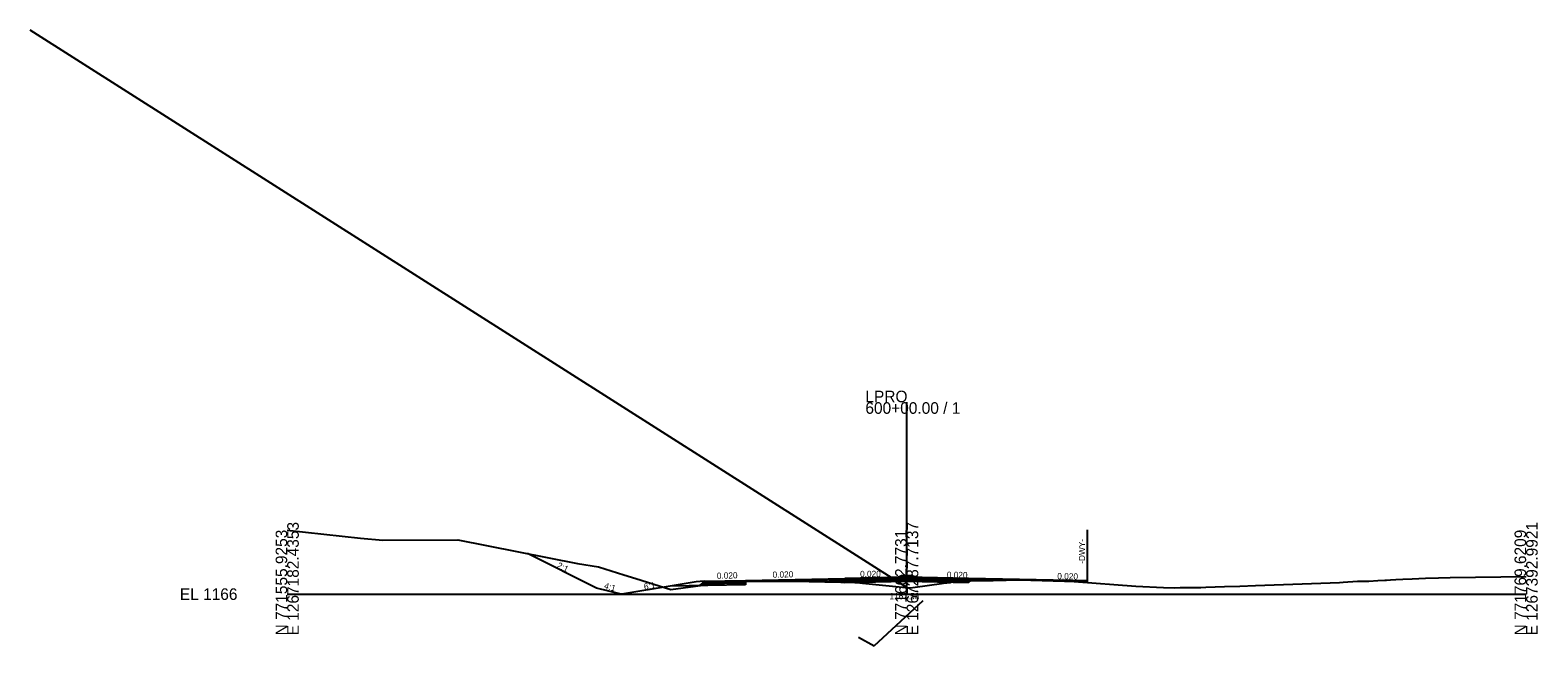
# Model space of a CAD drawing. Extents: x -3833 to 1267678, y -522 to 773248.
# Drawn here: x 937.8 to 1302.8, y 987.5 to 1136.6 of the extents above; entities that cross this region are included whole.
import ezdxf

# ---------------------------------------------------------------- set-up
doc = ezdxf.new("R2010")
doc.units = 0
for name, color, linetype in [('Exist Cross Section Cell', 7, 'Continuous'), ('Exist XS Center Line Elevation Label', 7, 'Continuous'), ('Exist XS Ground Line', 7, 'Continuous'), ('Prop CMT DNC', 7, 'Continuous'), ('Prop CMT Pvmt Course 1', 7, 'Continuous'), ('Prop CMT Pvmt Course 2', 7, 'Continuous'), ('Prop CMT Pvmt Course 4', 7, 'Continuous'), ('Prop CMT Shld Paved Course 1', 7, 'Continuous'), ('Prop CMT Shld Paved Course 2', 7, 'Continuous'), ('Prop CMT Shld Paved Course 4', 7, 'Continuous'), ('Prop CMT Slope Grass', 7, 'Continuous'), ('Prop CMT Subgrade Earthwork', 7, 'Continuous'), ('Prop Conc Curb and Gutter', 7, 'Continuous'), ('Prop Corridor Mesh Bottom', 7, 'Continuous'), ('Prop XS Ditch Slope Text', 7, 'Continuous'), ('Prop XS Finish Grade', 7, 'Continuous'), ('Prop XS SE Text', 7, 'Continuous'), ('Prop XS Shear Point Element', 7, 'Continuous'), ('Prop XS Shear Point Label', 7, 'Continuous'), ('Scratch_Level_1', 7, 'Continuous'), ('Scratch_Level_5', 7, 'Continuous')]:
    doc.layers.add(name, color=color, linetype=linetype)

msp = doc.modelspace()

# ---------------------------------------------------------------- linework, layer by layer
at = {"layer": 'Exist Cross Section Cell'}
for p, q in [((1150, 1000), (1150, 1046.49)), ((1000, 1000), (1150, 1000)), ((1150, 1000), (1300, 1000))]:
    msp.add_line(p, q, dxfattribs=at)
at = {"layer": 'Exist XS Ground Line'}
for p, q in [((1000, 1015.5), (1017.77, 1013.59)), ((1017.77, 1013.59), (1023.18, 1013.11)), ((1023.18, 1013.11), (1041.35, 1013.17)), ((1041.35, 1013.17), (1070.26, 1007.43)), ((1070.26, 1007.43), (1075.35, 1006.63)), ((1075.35, 1006.63), (1081.51, 1004.66)), ((1081.51, 1004.66), (1084.42, 1003.76)), ((1278.81, 1003.94), (1281.57, 1004.02)), ((1281.57, 1004.02), (1300, 1004.27)), ((1084.42, 1003.76), (1092.93, 1001.15)), ((1092.93, 1001.15), (1104.86, 1002.77)), ((1104.86, 1002.77), (1106.77, 1002.98)), ((1106.77, 1002.98), (1109.97, 1003.12)), ((1109.97, 1003.12), (1110.46, 1003.12)), ((1110.46, 1003.12), (1111.83, 1003.13)), ((1111.83, 1003.13), (1122.5, 1003.16)), ((1122.5, 1003.16), (1134.09, 1002.93)), ((1134.09, 1002.93), (1135.87, 1002.89)), ((1135.87, 1002.89), (1136.2, 1002.87)), ((1136.2, 1002.87), (1138.68, 1002.74)), ((1138.68, 1002.74), (1139.33, 1002.67)), ((1139.33, 1002.67), (1149.03, 1001.67)), ((1149.03, 1001.67), (1150, 1001.58)), ((1150, 1001.58), (1150.87, 1001.49)), ((1150.87, 1001.49), (1152.03, 1001.66)), ((1152.03, 1001.66), (1158.46, 1002.61)), ((1158.46, 1002.61), (1158.92, 1002.66)), ((1158.92, 1002.66), (1160.5, 1002.85)), ((1160.5, 1002.85), (1160.9, 1003.08)), ((1160.9, 1003.08), (1163.34, 1003.19)), ((1163.34, 1003.19), (1164.61, 1003.25)), ((1164.61, 1003.25), (1164.95, 1003.24)), ((1164.95, 1003.24), (1165.49, 1003.25)), ((1165.49, 1003.25), (1170.95, 1003.33)), ((1170.95, 1003.33), (1177.29, 1003.43)), ((1177.29, 1003.43), (1188.21, 1003.17)), ((1188.21, 1003.17), (1189.39, 1003.14)), ((1189.39, 1003.14), (1190.57, 1003.07)), ((1190.57, 1003.07), (1205.46, 1001.91)), ((1205.46, 1001.91), (1212.19, 1001.57)), ((1212.19, 1001.57), (1214.82, 1001.56)), ((1214.82, 1001.56), (1216.21, 1001.57)), ((1216.21, 1001.57), (1218.06, 1001.58)), ((1218.06, 1001.58), (1219.86, 1001.6)), ((1219.86, 1001.6), (1221.24, 1001.62)), ((1221.24, 1001.62), (1222.43, 1001.69)), ((1222.43, 1001.69), (1226.96, 1001.85)), ((1226.96, 1001.85), (1230.69, 1001.94)), ((1230.69, 1001.94), (1234.49, 1002.07)), ((1234.49, 1002.07), (1254.8, 1002.84)), ((1254.8, 1002.84), (1255.7, 1002.93)), ((1255.7, 1002.93), (1259.14, 1003.1)), ((1259.14, 1003.1), (1261.92, 1003.16)), ((1261.92, 1003.16), (1264.13, 1003.29)), ((1264.13, 1003.29), (1265.75, 1003.36)), ((1265.75, 1003.36), (1266.22, 1003.39)), ((1266.22, 1003.39), (1267.15, 1003.45)), ((1267.15, 1003.45), (1268.43, 1003.51)), ((1268.43, 1003.51), (1270.14, 1003.61)), ((1270.14, 1003.61), (1272.44, 1003.73)), ((1272.44, 1003.73), (1275.61, 1003.84)), ((1275.61, 1003.84), (1278.81, 1003.94))]:
    msp.add_line(p, q, dxfattribs=at)
at = {"layer": 'Prop CMT Pvmt Course 1'}
for p, q in [((1147.75, 1004.06), (1147, 1004.05)), ((1152.82, 1004.05), (1153, 1004.05)), ((1111, 1003.33), (1135, 1003.81)), ((1111, 1003.12), (1111, 1003.33)), ((1111, 1003.33), (1111, 1003.33)), ((1135, 1003.81), (1135, 1003.81)), ((1135, 1003.81), (1135, 1003.81)), ((1135, 1003.81), (1135, 1003.56)), ((1135, 1003.56), (1135, 1003.56)), ((1147, 1003.8), (1147.75, 1003.81)), ((1153, 1003.8), (1152.82, 1003.8)), ((1193.7, 1003.23), (1165, 1003.81)), ((1165, 1003.81), (1165, 1003.81)), ((1165, 1003.81), (1165, 1003.24)), ((1165, 1003.56), (1177.29, 1003.43)), ((1189.78, 1003.12), (1193.7, 1002.98)), ((1193.7, 1002.98), (1193.7, 1003.23)), ((1193.7, 1003.23), (1193.7, 1003.23)), ((1193.7, 1003.23), (1193.7, 1003.23)), ((1193.7, 1002.98), (1193.7, 1002.98))]:
    msp.add_line(p, q, dxfattribs=at)
at = {"layer": 'Prop CMT Pvmt Course 2'}
for p, q in [((1150, 1003.86), (1135, 1003.56)), ((1135, 1003.56), (1135, 1003.56)), ((1135, 1003.56), (1135, 1003.23)), ((1135, 1003.22), (1150, 1003.53)), ((1135, 1003.23), (1135, 1003.22)), ((1147.75, 1003.81), (1147, 1003.8)), ((1165, 1003.56), (1150, 1003.86)), ((1150, 1003.86), (1150, 1003.86)), ((1150, 1003.86), (1150, 1003.86)), ((1150, 1003.53), (1150, 1003.53)), ((1150, 1003.53), (1150, 1003.53)), ((1150, 1003.53), (1165, 1003.22)), ((1152.25, 1003.81), (1152.82, 1003.8)), ((1152.82, 1003.8), (1153, 1003.8)), ((1165, 1003.56), (1165, 1003.56)), ((1165, 1003.22), (1165, 1003.22))]:
    msp.add_line(p, q, dxfattribs=at)
at = {"layer": 'Prop CMT Pvmt Course 4'}
for p, q in [((1147, 1004.05), (1147, 1003.01)), ((1148, 1004.07), (1148, 1003.03)), ((1152, 1004.07), (1152, 1003.03)), ((1153, 1004.05), (1153, 1003.01)), ((1135, 1002.76), (1135, 1003.23)), ((1135, 1003.23), (1135, 1003.23)), ((1135, 1003.23), (1135, 1003.22)), ((1150, 1003.53), (1150, 1003.53)), ((1150, 1003.53), (1150, 1003.53)), ((1165, 1003.22), (1165, 1003.22)), ((1165, 1003.22), (1165, 1003.22))]:
    msp.add_line(p, q, dxfattribs=at)
at = {"layer": 'Prop CMT Shld Paved Course 1'}
for p, q in [((1150, 1004.11), (1135, 1003.81)), ((1165, 1003.81), (1150, 1004.11)), ((1150, 1004.11), (1150, 1004.11)), ((1150, 1004.11), (1150, 1004.11)), ((1150, 1004.11), (1150, 1004.11)), ((1150, 1004.11), (1150, 1004.11)), ((1100.74, 1002.87), (1101, 1003.13)), ((1111, 1003.08), (1100.74, 1002.87)), ((1101, 1003.13), (1111, 1003.33)), ((1101, 1003.13), (1101, 1003.13)), ((1111, 1003.33), (1111, 1003.33)), ((1111, 1003.33), (1111, 1003.33)), ((1111, 1003.33), (1111, 1003.08)), ((1111, 1003.08), (1111, 1003.08)), ((1135, 1003.81), (1135, 1003.81)), ((1135, 1003.81), (1135, 1003.56)), ((1150, 1003.86), (1150, 1003.86)), ((1150, 1003.86), (1150, 1003.86)), ((1150, 1003.86), (1150, 1003.86)), ((1165, 1003.56), (1165, 1003.81)), ((1165, 1003.81), (1165, 1003.81))]:
    msp.add_line(p, q, dxfattribs=at)
at = {"layer": 'Prop CMT Shld Paved Course 2'}
for p, q in [((1100.4, 1002.53), (1100.74, 1002.87)), ((1100.74, 1002.87), (1100.74, 1002.87)), ((1111, 1003.08), (1111, 1003.08)), ((1111, 1003.08), (1111, 1003.08)), ((1111, 1002.74), (1111, 1002.74)), ((1113.8, 1003.13), (1122.5, 1003.16)), ((1113.8, 1003.13), (1113.8, 1003.13)), ((1122.5, 1003.31), (1113.81, 1003.13)), ((1135, 1003.56), (1122.5, 1003.31)), ((1122.5, 1003.31), (1122.5, 1003.31)), ((1122.5, 1003.16), (1122.5, 1003.16)), ((1122.5, 1003.16), (1122.5, 1003.16)), ((1122.5, 1003.16), (1127.2, 1003.07)), ((1127.2, 1003.07), (1135, 1003.22)), ((1127.2, 1003.07), (1127.2, 1003.07)), ((1134.09, 1003.54), (1134.09, 1003.54)), ((1134.09, 1003.2), (1134.09, 1003.2)), ((1135, 1003.22), (1135, 1003.56)), ((1135, 1003.56), (1135, 1003.56)), ((1165, 1003.56), (1165, 1003.56)), ((1165, 1003.56), (1165, 1003.56)), ((1165, 1003.24), (1165, 1003.24)), ((1170.95, 1003.44), (1170.95, 1003.44)), ((1170.95, 1003.33), (1170.95, 1003.33)), ((1173.98, 1003.38), (1173.98, 1003.38)), ((1190.57, 1003.07), (1190.57, 1003.07)), ((1193.7, 1002.83), (1193.7, 1002.98)), ((1193.7, 1002.98), (1193.7, 1002.98)), ((1193.7, 1002.83), (1193.7, 1002.83))]:
    msp.add_line(p, q, dxfattribs=at)
at = {"layer": 'Prop CMT Shld Paved Course 4'}
for p, q in [((1099.94, 1002.06), (1100.4, 1002.53)), ((1100.4, 1002.53), (1100.9, 1002.54)), ((1100.9, 1002.54), (1111, 1002.74)), ((1111, 1002.74), (1111, 1002.28))]:
    msp.add_line(p, q, dxfattribs=at)
at = {"layer": 'Prop CMT Slope Grass'}
for p, q in [((1099, 1002.97), (1092.72, 1001.92)), ((1101, 1003.13), (1099, 1002.97))]:
    msp.add_line(p, q, dxfattribs=at)
at = {"layer": 'Prop CMT Subgrade Earthwork'}
for p, q in [((1111, 1002.28), (1092.72, 1001.92)), ((1111, 1003.12), (1111, 1002.28)), ((1149.99, 1003.07), (1135, 1002.76)), ((1135, 1002.76), (1135, 1002.91)), ((1165, 1002.76), (1149.99, 1003.07)), ((1165, 1003.24), (1165, 1002.76))]:
    msp.add_line(p, q, dxfattribs=at)
at = {"layer": 'Prop Conc Curb and Gutter'}
for p, q in [((1148, 1004.06), (1148.01, 1004.23)), ((1148, 1004.06), (1148, 1003.93)), ((1148.01, 1004.23), (1148.76, 1004.48)), ((1148.76, 1004.48), (1150, 1004.5)), ((1151.24, 1004.47), (1150, 1004.5)), ((1151.99, 1004.22), (1151.24, 1004.47)), ((1152, 1004.06), (1151.99, 1004.22)), ((1152, 1004.06), (1152, 1003.93)), ((1148, 1003.93), (1150, 1003.93)), ((1152, 1003.93), (1150, 1003.93))]:
    msp.add_line(p, q, dxfattribs=at)
at = {"layer": 'Prop Corridor Mesh Bottom'}
for p, q in [((1111, 1003.33), (1111, 1003.08)), ((1135, 1003.81), (1135, 1003.56)), ((1165, 1003.81), (1165, 1003.56)), ((1193.7, 1003.23), (1193.7, 1002.98))]:
    msp.add_line(p, q, dxfattribs=at)
at = {"layer": 'Prop XS Finish Grade'}
for p, q in [((1074.9, 1001.47), (1058.17, 1009.83)), ((1080.9, 999.97), (1074.9, 1001.47)), ((1092.72, 1001.92), (1081, 999.97)), ((1080.95, 999.97), (1080.9, 999.97)), ((1081, 999.97), (1080.95, 999.97))]:
    msp.add_line(p, q, dxfattribs=at)
at = {"layer": 'Prop XS Shear Point Element'}
msp.add_line((1193.7, 1015.58), (1193.7, 1002.83), dxfattribs=at)
at = {"layer": 'Scratch_Level_1'}
msp.add_line((1150, 1001.58), (937.75, 1136.63), dxfattribs=at)
at = {"layer": 'Scratch_Level_5'}
for p, q in [((1142.15, 987.47), (1154.01, 998.49)), ((1138.36, 989.57), (1142.15, 987.47))]:
    msp.add_line(p, q, dxfattribs=at)

# ---------------------------------------------------------------- texts
at = {"layer": 'Exist Cross Section Cell'}
for s, p in [('LPRO', (1140, 1046.49)), ('600+00.00 / 1', (1140, 1043.69)), ('EL 1166', (974, 998.6))]:
    msp.add_text(s, height=2.8, dxfattribs=at).set_placement(p)
for s, p in [('N 771555.9253', (1000, 990)), ('E 1267182.4353', (1002.8, 990)), ('N 771662.7731', (1150, 990)), ('E 1267287.7137', (1152.8, 990)), ('N 771769.6209', (1300, 990)), ('E 1267392.9921', (1302.8, 990))]:
    msp.add_text(s, height=2.8, rotation=90, dxfattribs=at).set_placement(p)
at = {"layer": 'Exist XS Center Line Elevation Label'}
msp.add_text('1167.58', height=1.5, dxfattribs=at).set_placement((1145.84, 998.76))
at = {"layer": 'Prop CMT DNC'}
for p in [(1054.32, 1010.6), (1150, 1004.11), (1150, 1004.11), (1101, 1003.13), (1111, 1003.33), (1111, 1003.33), (1135, 1003.81), (1135, 1003.81), (1165, 1003.81), (1165, 1003.81), (1193.7, 1003.23), (1193.7, 1003.23), (1241.54, 1002.34), (1080.95, 999.97), (1081, 999.97)]:
    msp.add_text('X', height=0.00025, dxfattribs=at).set_placement(p)
at = {"layer": 'Prop XS Ditch Slope Text'}
for s, rotation, p in [('2:1', 334.1731, (1065.17, 1006.47)), ('4:1', 343.7547, (1076.62, 1001.4)), ('6:1', 9.0286, (1086.48, 1001.05))]:
    msp.add_text(s, height=1.5, rotation=rotation, dxfattribs=at).set_placement(p)
at = {"layer": 'Prop XS SE Text'}
for rotation, p in [(1.397, (1104.05, 1003.7)), (1.397, (1117.55, 1003.95)), (0.2693, (1138.72, 1004.14)), (358.8542, (1159.71, 1003.96)), (358.8542, (1186.46, 1003.62))]:
    msp.add_text('0.020', height=1.5, rotation=rotation, dxfattribs=at).set_placement(p)
at = {"layer": 'Prop XS Shear Point Label'}
msp.add_text('-DWY-', height=1.5, rotation=90, dxfattribs=at).set_placement((1193.2, 1007.35))

doc.saveas('drawing.dxf')
